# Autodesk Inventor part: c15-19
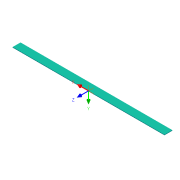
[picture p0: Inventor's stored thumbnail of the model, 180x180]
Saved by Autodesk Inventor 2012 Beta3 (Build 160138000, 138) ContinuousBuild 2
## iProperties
Created: 2011-02
Part Number: c15-19
Material: Default
Document SubType Name: Modeling
Designer: Beta-8540w
Density: 1 g/cm^3
Author: Beta-8540w
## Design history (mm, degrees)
sketch "Sketch1"
  geometry: L1 (-152.4, 7.938)-(152.4, 7.938); L2 (152.4, 7.938)-(152.4, -7.938); L3 (152.4, -7.938)-(-152.4, -7.938); L4 (-152.4, -7.938)-(-152.4, 7.938); 3 further points
  constraints: 8 end point, 2 midpoint, 2 parallel, 1 horizontal, 1 horizontal alignment, 1 perpendicular, 1 vertical alignment
  dimensions: "length" = 304.8 distance of L1.start L1.end; "d1" = 15.875 distance of L1.end L2.end
extrude "Extrusion1" new body sketch "Sketch1" taper "d3" = 0 deg; distance "thickness" = 1
body "Solid1"
other parameters: "d4" = 0, "d5" = 0, "d6" = 0, "d7" = 0, "d8" = 0, "d9" = 0
